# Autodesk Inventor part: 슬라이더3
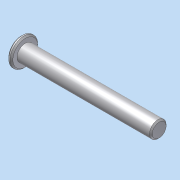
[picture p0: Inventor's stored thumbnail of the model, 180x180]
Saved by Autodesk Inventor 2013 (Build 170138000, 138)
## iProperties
Company: 한국ATC센터
Created: 2015-04
Part Number: 슬라이더3
Document SubType Name: Modeling
Designer: KYOUNG IL JANG
Density: 7.85 g/cm^3
Material: 강철
Mass: 92.8999 g
Surface Area: 43.7403 cm^2
Volume: 11.8344 cm^3
Author: KYOUNG IL JANG
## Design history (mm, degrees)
sketch "스케치1"
  geometry: L1 (0, 0)-(0, 10); L2 (0, 10)-(-3, 10); L3 (-3, 10)-(-3, 6); L4 (-3, 6)-(-100, 6); L5 (-100, 6)-(-100, 0); L6 (-100, 0)-(0, 0)
  constraints: 12 end point, 4 parallel, 1 perpendicular, 1 vertical
  dimensions: "d0" = 12 diameter of L4 L6; "d1" = 20 diameter of L2 L6; "d2" = 3 distance between parallel lines of L3 L1; "d3" = 100 distance between parallel lines of L5 L1
revolve "회전1" sketch "스케치1" stored, may be unused: angle "d4" = 90 deg
chamfer "모따기1" distance "d5" = 1; stored, may be unused: second distance "d6" = 2, angle "d7" = 45 deg
node "솔리드1"
